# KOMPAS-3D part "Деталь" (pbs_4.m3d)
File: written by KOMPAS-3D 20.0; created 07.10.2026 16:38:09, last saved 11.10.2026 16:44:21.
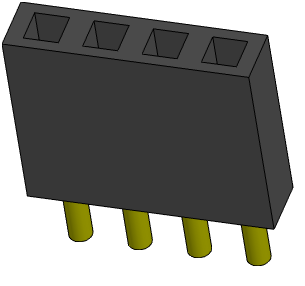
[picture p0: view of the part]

Document properties: Полное имя файла: D:\myProjects\Progect_esp32\box_compas\pbs_4.m3d

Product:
- Part/product: Деталь
    Масса: 0.0012713

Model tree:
1. Эскиз:1
2. Элемент выдавливания:1
     Расстояние 1 = 8.5
3. Эскиз:2  (with: Элемент выдавливания:1)
4. Элемент выдавливания:2
     Расстояние 1 = 3
5. Массив по сетке:2  (with: Элемент выдавливания:2, Эскиз:2)  (4 pattern instances)
     Шаг 1 = 2.54; Угол раствора = 90
6. Эскиз:3  (with: Элемент выдавливания:1)
7. Элемент выдавливания:3
     Расстояние 2 = 8
8. Массив по сетке:3  (with: Элемент выдавливания:3, Эскиз:3)  (5 pattern instances)
     Шаг 1 = 2.54; Угол раствора = 90; Геометрический массив = 128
